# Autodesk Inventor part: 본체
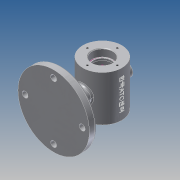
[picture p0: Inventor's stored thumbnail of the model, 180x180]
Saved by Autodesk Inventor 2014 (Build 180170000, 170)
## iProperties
Created: 2018-12
Part Number: 본체
Material: 알루미늄 6061
Document SubType Name: Modeling
Designer: kb542-14
Density: 2.71 g/cm^3
Appearance: 알루미늄 - 평지
Mass: 687.619 g
Surface Area: 555.459 cm^2
Volume: 253.734 cm^3
Author: kb542-14
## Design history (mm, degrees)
sketch "스케치1"
  geometry: C1 r 30 at (0, 0); 1 further point
  constraints: 1 centre point, 1 coincident
  dimensions: "d0" = 60 diameter of C1
extrude "돌출1" new body sketch "스케치1" stored distance "d1" = 70; taper "d2" = 0 deg
node "작업 평면1"
sketch "스케치2"
  geometry: C1 r 55 at (0, 0); 1 further point
  constraints: 1 centre point, 1 coincident
  dimensions: "d4" = 110 diameter of C1
extrude "돌출2" join sketch "스케치2" distance "d5" = 11; taper "d6" = 0 deg
sketch "스케치4"
  geometry: C1 r 12 at (0, 0); 1 further point
  constraints: 1 centre point, 1 coincident
  dimensions: "d14" = 24 diameter of C1
extrude "돌출3" join sketch "스케치4" stored distance "d15" = 30; taper "d16" = 0 deg
fillet "모깎기2" dims "d18" = 3
sketch "스케치5"
  geometry: L1 (55, -64)-(-55, -64) reference; L2 (0, -64)-(-55, -64); L3 (0, -64)-(55, -64); L4 (-55, -64)-(0, -49.263); L5 (0, -49.263)-(0, -64); 1 further point
  constraints: 8 end point, 2 collinear, 1 horizontal, 1 midpoint, 1 perpendicular
  dimensions: "d19" = 55 distance of L2.start L2.end; "d20" = 180 deg angle of L2 L3 (derived); "d21" = 15 deg angle of L2 L4
revolve "회전2" sketch "스케치5" stored, may be unused: angle "d22" = 90 deg
fillet "모깎기3" dims "d23" = 3
fillet "모깎기4" dims "d24" = 3
node "작업 평면2"
sketch "스케치6"
  geometry: C1 r 10 at (0, 0); 1 further point
  constraints: 1 centre point, 1 coincident
  dimensions: "d26" = 20 diameter of C1
extrude "돌출4" join sketch "스케치6" stored distance "d27" = 30; taper "d28" = 0 deg
sketch "스케치7"
  geometry: C1 r 10 at (0, 0) reference; C2 r 5 at (0, 0)
  constraints: 1 centre point, 1 coincident
  dimensions: "d29" = 10 diameter of C2
extrude "돌출5" cut sketch "스케치7" distance "d30" = 30; taper "d31" = 0 deg
sketch "스케치8"
  geometry: C1 r 30 at (0, 0) reference; C2 r 16 at (0, 0)
  constraints: 1 centre point, 1 coincident
  dimensions: "d32" = 32 diameter of C2
extrude "돌출6" cut sketch "스케치8" distance "d33" = 12; taper "d34" = 0 deg
sketch "스케치9"
  geometry: C1 r 16 at (0, 0) reference
fillet "모깎기5" dims "d35" = 0.3
sketch "스케치10"
  geometry: C1 r 15.7 at (0, 0) reference; C2 r 14 at (0, 0)
  constraints: 1 centre point, 1 coincident
  dimensions: "d36" = 28 diameter of C2
extrude "돌출7" cut sketch "스케치10" distance "d37" = 3; taper "d38" = 0 deg
sketch "스케치11"
  geometry: C1 r 14 at (0, 0) reference; C2 r 25 at (0, 0)
  constraints: 1 centre point, 1 coincident
  dimensions: "d39" = 50 diameter of C2
extrude "돌출8" cut sketch "스케치11" distance "d40" = 40; taper "d41" = 0 deg
fillet "모깎기6" dims "d42" = 3
sketch "스케치12"
  geometry: C1 r 30 at (0, 0) reference; C2 r 16 at (0, 0)
  constraints: 1 centre point, 1 coincident
  dimensions: "d43" = 32 diameter of C2
extrude "돌출9" cut sketch "스케치12" distance "d44" = 12; taper "d45" = 0 deg
fillet "모깎기7" dims "d46" = 0.3
sketch "스케치13"
  geometry: C1 r 15.7 at (0, 0) reference; C2 r 14 at (0, 0)
  constraints: 1 centre point, 1 coincident
  dimensions: "d47" = 28 diameter of C2
extrude "돌출10" cut sketch "스케치13" distance "d48" = 3; taper "d49" = 0 deg
fillet "모깎기8" dims "d50" = 3
chamfer "모따기1" distance "d51" = 1; stored, may be unused: second distance "d52" = 2, angle "d53" = 45 deg
chamfer "모따기2" distance "d54" = 1; stored, may be unused: second distance "d55" = 2, angle "d56" = 45 deg
chamfer "모따기3" distance "d57" = 1; stored, may be unused: second distance "d58" = 2, angle "d59" = 45 deg
sketch "스케치14" dims "d60" = 88
  geometry: C1 r 55 at (0, 0) reference; C2 r 5 at (0, 0) reference; C3 r 4.5 at (0, 44); C4 r 4.5 at (-44, 0); C5 r 4.5 at (0, -44); C6 r 4.5 at (44, 0); 2 further points
  constraints: 4 centre point, 2 coincident, 1 vertical alignment, 11 other
  dimensions: "d61" = 9 diameter of C3; "d64" = 360 deg dimension on C1.centre C3.centre (derived)
extrude "돌출11" cut sketch "스케치14" distance "d66" = 10; taper "d67" = 0 deg
sketch "스케치15"
  geometry: C1 r 4.5 at (0, 0) reference; C2 r 7 at (0, 0); 1 further point
  constraints: 1 centre point, 1 coincident
  dimensions: "d68" = 14 diameter of C2
extrude "돌출12" cut sketch "스케치15" distance "d69" = 10; taper "d70" = 0 deg
sketch "스케치16"
  geometry: C1 r 4.5 at (0, 0) reference; C2 r 7 at (0, 0); 1 further point
  constraints: 1 centre point, 1 coincident
  dimensions: "d71" = 14 diameter of C2
extrude "돌출13" cut sketch "스케치16" distance "d72" = 10; taper "d73" = 0 deg
sketch "스케치17"
  geometry: C1 r 4.5 at (0, 0) reference; C2 r 7 at (0, 0); 1 further point
  constraints: 1 centre point, 1 coincident
  dimensions: "d74" = 14 diameter of C2
extrude "돌출14" cut sketch "스케치17" distance "d75" = 10; taper "d76" = 0 deg
sketch "스케치18"
  geometry: C1 r 4.5 at (0, 0) reference; C2 r 7 at (0, 0); 1 further point
  constraints: 1 centre point, 1 coincident
  dimensions: "d77" = 14 diameter of C2
extrude "돌출15" cut sketch "스케치18" distance "d78" = 10; taper "d79" = 0 deg
fillet "모깎기9" dims "d80" = 3
sketch "스케치19" dims "d81" = 46
  geometry: C1 r 17 at (0, 0) reference; 2 further points
  constraints: 1 coincident, 1 vertical alignment, 2 other
hole "구멍1" sketch "스케치19" at (0, 23) diameter "d82" = 3.242; stored, may be unused: countersink angle "d86" = 90 deg, drill point angle "d88" = 118 deg; dims "d83" = 8, "d84" = 4, "d85" = 2, "d87" = 10
sketch "스케치20"
  geometry: C1 r 17 at (0, 0) reference; C2 r 23 at (0, 0); C3 r 1.621 at (0, 23) reference; 1 further point
  constraints: 2 coincident, 1 centre point
  dimensions: "d92" = 46 diameter of C2
hole "구멍2" sketch "스케치20" at (0, 23) diameter "d93" = 3.242; stored, may be unused: countersink angle "d97" = 90 deg, drill point angle "d99" = 118 deg; dims "d94" = 8, "d95" = 4, "d96" = 2, "d98" = 10
node "작업 평면3"
sketch "스케치21"
  geometry: L1 (30, 35)-(-30, 35) reference; L2 (3.602, 24.848)-(3.602, -24.848); L3 (3.602, -24.848)-(-3.602, -24.848); L4 (-3.602, -24.848)-(-3.602, 24.848); L5 (-3.602, 24.848)-(3.602, 24.848); 4 further points
  constraints: 2 midpoint, 1 horizontal alignment, 1 vertical alignment, 2 other
  dimensions: "d104" = 35 distance from line of L1 point (0, 0); "d105" = 30 horizontal distance of L1.start point (0, 0)
feature "엠보싱1" sketch "스케치21" dims "d0" = 60, "d19" = 55, "d20" = 180 deg (derived), "d21" = 15 deg, "d106" = 0.5, "d107" = 0
node "솔리드1"
pattern_circular "원형 패턴1" dims angle "d90" = 360 deg
pattern_circular "원형 패턴2" dims angle "d101" = 360 deg
other parameters: "d3" = -75, "d25" = 37, "d103" = 31
